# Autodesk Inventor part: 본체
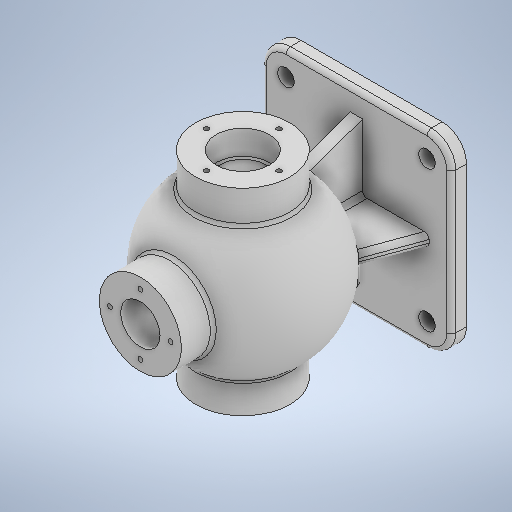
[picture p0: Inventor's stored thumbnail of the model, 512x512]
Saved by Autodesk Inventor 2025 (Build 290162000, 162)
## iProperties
Created: 2025-08
Part Number: 본체
Material: 일반
Document SubType Name: Modeling
Designer: infra017
Density: 1 g/cm^3
Appearance: 기본값
Author: infra017
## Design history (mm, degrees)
sketch "스케치1"
  geometry: L1 (-62.5, 62.5)-(62.5, 62.5); L2 (62.5, 62.5)-(62.5, -62.5); L3 (62.5, -62.5)-(-62.5, -62.5); L4 (-62.5, -62.5)-(-62.5, 62.5); L5 (-62.5, 62.5)-(62.5, -62.5); L6 (62.5, 62.5)-(-62.5, -62.5); 1 further point
  constraints: 12 end point, 2 midpoint, 2 parallel, 1 horizontal, 1 perpendicular
  dimensions: "d0" = 125 distance of L1.start L1.end; "d1" = 125 distance of L3.end L1.start
extrude "돌출1" new body sketch "스케치1" distance "d2" = 10; taper "d3" = 0 deg
node "작업 평면1"
sketch "스케치2"
  geometry: L1 (-54, 0.116)-(54, -0.116); A1 r 54 centre (0, 0) between (54, -0.116) and (-54, 0.116); 1 further point
  constraints: 2 end point, 2 point on circle, 1 centre point, 1 coincident
  dimensions: "d5" = 108 diameter of A1; "d6" = 108 distance of L1.start L1.end; "d7" = 107.99975 horizontal distance of L1.start L1.end
revolve "회전1" sketch "스케치2" stored, may be unused: angle "d8" = 90 deg
sketch "스케치3"
  geometry: L1 (-27, 152.563)-(27, 152.563); L2 (27, 152.563)-(27, 131.765); L3 (27, 131.765)-(-27, 131.765); L4 (-27, 131.765)-(-27, 152.563); L5 (0, 152.563)-(0, 131.765); L6 (-64.215, 116)-(-44.215, 116); L7 (-44.215, 116)-(-44.215, 54); L8 (-44.215, 54)-(-64.215, 54); L9 (-64.215, 54)-(-64.215, 116); L10 (44, 116)-(65.785, 116); L11 (65.785, 116)-(65.785, 54); L12 (65.785, 54)-(44, 54); L13 (44, 54)-(44, 116); L14 (-64.215, 85)-(-44.215, 85); L15 (44, 85)-(65.785, 85); L16 (62.5, 0)-(-62.5, 0) reference; A1 r 54 centre (0, 85) between (27, 131.765) and (-44.215, 54) reference; 8 further points
  constraints: 30 end point, 7 midpoint, 6 parallel, 3 horizontal, 3 perpendicular, 2 horizontal alignment, 2 point on circle, 1 coincident, 1 vertical alignment
  dimensions: "d9" = 54 distance of L1.start L1.end; "d10" = 20.79787 distance of L1.end L2.end; "d11" = 20 distance of L6.start L6.end; "d12" = 130 distance of L10.end L6.start; "d13" = 62 distance of L8.end L6.start; "d14" = 62 distance of L10.end L11.end; "d15" = 44 distance from line of point (0, 0) L13
revolve "회전2" stored, may be unused: angle "d16" = 90 deg
revolve "회전3" stored, may be unused: angle "d17" = 90 deg
sketch "스케치4"
  geometry: C1 r 17.5 at (0, 0); C2 r 31 at (0, 0) reference; 1 further point
  constraints: 1 centre point, 1 coincident
  dimensions: "d18" = 35 diameter of C1
extrude "돌출2" cut sketch "스케치4" distance "d19" = 16; taper "d20" = 0 deg
sketch "스케치5"
  geometry: C1 r 17.5 at (0, 0) reference; C2 r 17.5 at (0, 0); 1 further point
  constraints: 1 centre point, 1 coincident
extrude "돌출3" cut sketch "스케치5" distance "d21" = 16; taper "d22" = 0 deg
sketch "스케치6"
  geometry: C1 r 13 at (0, 0); 1 further point
  constraints: 1 centre point, 1 coincident
  dimensions: "d23" = 26 diameter of C1
extrude "돌출4" cut sketch "스케치6" distance "d24" = 28.5; taper "d25" = 0 deg
sketch "스케치7"
  geometry: L1 (-37.34, 44.04)-(-49.686, 10.121); L2 (35.742, 43.431)-(47.91, 10); L3 (-62.5, 0)-(-62.5, 10) reference; L4 (62.5, 0)-(62.5, 10) reference; L5 (-37.34, 44.04)-(-36.812, 45.492); L6 (35.742, 43.431)-(35.441, 44.258); L7 (-36.812, 45.492)-(35.441, 44.258); L8 (-49.686, 10.121)-(47.91, 10); L9 (-49.686, 10.121)-(47.91, 10); A1 r 54 centre (0, 85) between (-44.215, 54) and (-44.215, 116) reference; 2 further points; 1 other entity
  constraints: 14 end point, 2 point on circle, 2 point on line, 1 collinear, 1 midpoint, 1 other
  dimensions: "d28" = 20 deg angle of L3 L1; "d29" = 12 distance from line of L3.end L1; "d30" = 12 distance from line of point (62.5, 5) L2; "d31" = 20 deg angle of L4 L2
extrude "돌출5" join sketch "스케치7" stored distance "d32" = 8; taper "d33" = 0 deg
sketch "스케치8"
  geometry: L1 (-35.441, 44.258)-(-47.91, 10); L2 (62.5, 10)-(-62.5, 10) reference; L3 (35.441, 44.258)-(47.91, 10); L4 (-62.5, 0)-(-62.5, 10) reference; L5 (62.5, 0)-(62.5, 10) reference; L6 (-35.441, 44.258)-(35.441, 44.258); L7 (-47.91, 10)-(47.91, 10); A1 r 54 centre (0, 85) between (-27, 131.765) and (27, 131.765) reference; 3 further points
  constraints: 8 end point, 2 midpoint, 2 point on circle, 2 point on line, 1 collinear
  dimensions: "d34" = 20 deg angle of L4 L1; "d35" = 12 distance from line of point (-62.5, 5) L1; "d36" = 12 distance from line of point (62.5, 5) L3; "d37" = 20 deg angle of L5 L3
extrude "돌출6" join sketch "스케치8" stored distance "d38" = 8; taper "d39" = 0 deg
sketch "스케치9"
  geometry: L1 (46.5, -46.5)-(-46.5, -46.5); L2 (-46.5, -46.5)-(-46.5, 46.5); L3 (-46.5, 46.5)-(46.5, 46.5); L4 (46.5, 46.5)-(46.5, -46.5); L5 (46.5, -46.5)-(-46.5, 46.5); L6 (-46.5, -46.5)-(46.5, 46.5); 1 further point
  constraints: 12 end point, 2 midpoint, 2 parallel, 1 horizontal, 1 perpendicular
  dimensions: "d40" = 93 distance of L1.start L1.end; "d41" = 93 distance of L1.end L2.end
hole "구멍1" sketch "스케치9" at (46.5, -46.5), (-46.5, -46.5), (-46.5, 46.5), (46.5, 46.5) diameter "d42" = 11; stored, may be unused: countersink angle "d46" = 90 deg, drill point angle "d48" = 118 deg; dims "d43" = 6, "d44" = 4, "d45" = 2, "d47" = 8
sketch "스케치10"
  geometry: L1 (49.785, 102.5)-(49.785, 67.5) reference; L2 (44.215, 116)-(44.215, 54) reference; L3 (49.785, 100)-(44.215, 100); L4 (44.215, 100)-(44.215, 85); L5 (44.215, 85)-(49.785, 85); L6 (49.785, 85)-(49.785, 100); L7 (-44.215, 54)-(-44.215, 116) reference; L8 (-48.215, 67.5)-(-48.215, 102.5) reference; L9 (-44.215, 100)-(-48.215, 100); L10 (-48.215, 100)-(-48.215, 85); L11 (-48.215, 85)-(-44.215, 85); L12 (-44.215, 85)-(-44.215, 100); L13 (44.215, 100)-(44.215, 85); L14 (49.785, 100)-(49.785, 85); L15 (-44.215, 100)-(-44.215, 85); L16 (-48.215, 100)-(-48.215, 85); 5 further points
  constraints: 24 end point, 4 parallel, 3 collinear, 3 perpendicular, 2 horizontal, 2 midpoint, 2 point on line
  dimensions: "d49" = 15 distance between parallel lines of L5 L3; "d50" = 15 distance between parallel lines of L11 L9
revolve "회전4" sketch "스케치10" stored, may be unused: angle "d51" = 90 deg
sketch "스케치11"
  geometry: L1 (0, 44.258)-(0, 31) reference; L2 (0, 31)-(0, 44.258) reference; L3 (44.215, 116)-(44.215, 54) reference; L4 (-44.215, 54)-(-44.215, 116) reference; L5 (-27, 131.765)-(27, 131.765) reference; L6 (44.215, 85)-(-44.215, 85); C1 r 44 at (0, 85); A1 r 54 centre (0, 85) between (-36.812, 45.492) and (0, 31) reference; A2 r 54 centre (0, 85) between (0, 31) and (35.441, 44.258) reference; 3 further points
  constraints: 2 end point, 2 midpoint, 1 centre point, 1 coincident
  dimensions: "d52" = 88 diameter of C1
revolve "회전5" sketch "스케치11" stored, may be unused: angle "d55" = 360 deg
sketch "스케치12"
  geometry: C1 r 15 at (0, 0) reference; 1 further point
extrude "돌출7" cut sketch "스케치12" extent not by distance; stored distance "d56" = 0; taper "d57" = 0 deg
sketch "스케치13"
  geometry: L1 (0, 0)-(0, -24); C1 r 17.5 at (0, 0) reference; 8 further points
  constraints: 4 coincident, 2 end point, 1 vertical, 9 other
  dimensions: "d60" = 24 distance of L1.start L1.end; "d63" = 360 deg dimension on L1.start L1.end (derived)
hole "구멍2" sketch "스케치13" at (0, -24), (24, 0), (0, 24), (-24, 0) diameter "d65" = 3.242; stored, may be unused: countersink angle "d69" = 90 deg, drill point angle "d71" = 118 deg; dims "d66" = 12, "d67" = 4, "d68" = 2, "d70" = 15
sketch "스케치14"
  geometry: L1 (35.441, 0)-(0, 0) reference; L2 (0, 0)-(0, 20); L3 (0, 0)-(0, 35.441) reference; L4 (0, -36.812)-(0, 0) reference; L5 (35.441, 0)-(0, 0) reference; L6 (0, 0)-(0, 35.441) reference; L7 (0, 0)-(-35.441, 0) reference; L8 (-31, 44.215)-(31, 44.215) reference; L9 (31, -44.215)-(-31, -44.215) reference; L10 (4, 35.441)-(4, 4) reference; C1 r 13 at (0, 0) reference; C2 r 27 at (0, 0) reference; C3 r 27 at (0, 0) reference; 7 further points
  constraints: 4 coincident, 2 end point, 1 point on line, 9 other
  dimensions: "d75" = 20 distance of L1.end L2.end; "d78" = 360 deg dimension on C1.centre L2.end (derived)
hole "구멍3" sketch "스케치14" at (0, 20), (-20, 0), (0, -20), (20, 0) diameter "d80" = 3.242; stored, may be unused: countersink angle "d84" = 90 deg, drill point angle "d86" = 118 deg; dims "d81" = 9, "d82" = 4, "d83" = 2, "d85" = 11
fillet "모깎기1" dims "d87" = 3
fillet "모깎기2" dims "d88" = 3
fillet "모깎기3" dims "d89" = 3
fillet "모깎기4" dims "d90" = 3
fillet "모깎기5" dims "d91" = 16
fillet "모깎기6" dims "d92" = 3
fillet "모깎기7" dims "d93" = 3
fillet "모깎기8" dims "d94" = 3
node "솔리드1"
mirror "미러1"
node "투영된 루프1"
node "투영된 루프2"
node "투영된 루프3"
node "스케치 - 원형 패턴1" dims "d63" = 360 deg (derived)
node "투영된 루프4"
node "투영된 루프5"
node "스케치 - 원형 패턴2" dims "d78" = 360 deg (derived)
feature "A9D066F2-1C7D-4E18-AEED-F7BC21143FA4" dims "d42" = 11, "d43" = 6, "d44" = 4, "d45" = 2, "d46" = 90 deg, "d47" = 8, "d48" = 118 deg
other parameters: "d4" = 85
